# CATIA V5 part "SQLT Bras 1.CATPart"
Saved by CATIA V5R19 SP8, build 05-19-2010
Part number: SQLT Bras 1
Publications: "Droite.4", "Droite.5", "Droite.6", "Droite.7"
Bounding box of the stored display mesh (mm): x -1000 to 1000, y 0 to 0, z -2650 to 0
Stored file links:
  C:\Users\ThinkMotion\Desktop\EU_thinkMotion\iao\IAO_MMS_Groupe3\fovide\fovide\SQLT Bras 1.CATPart
  C:\Users\ThinkMotion\Desktop\EU_thinkMotion\iao\IAO_MMS_Groupe3\fovide\fovide\fovide.CATProduct
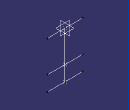
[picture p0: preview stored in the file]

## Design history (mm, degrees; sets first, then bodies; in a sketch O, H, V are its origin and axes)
Set1
  Point1 "Point.D": linked copy from another document
  Point2 "Point.F": linked copy from another document
  Point3 "Point.C": linked copy from another document
Set2 "set bras 1"
  Line1: type PtPt, FirstPoint Point1, SecondPoint Point2
  Line2: type Normal, RefPoint Point1, RefSkin yz-plane, Start -1000, End 1000
  Line3: type Normal, RefPoint Point2, RefSkin yz-plane, Start -1000, End 1000
  Line4: type Normal, RefPoint Point3, RefSkin yz-plane, Start -1000, End 1000
Body1 (main body)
